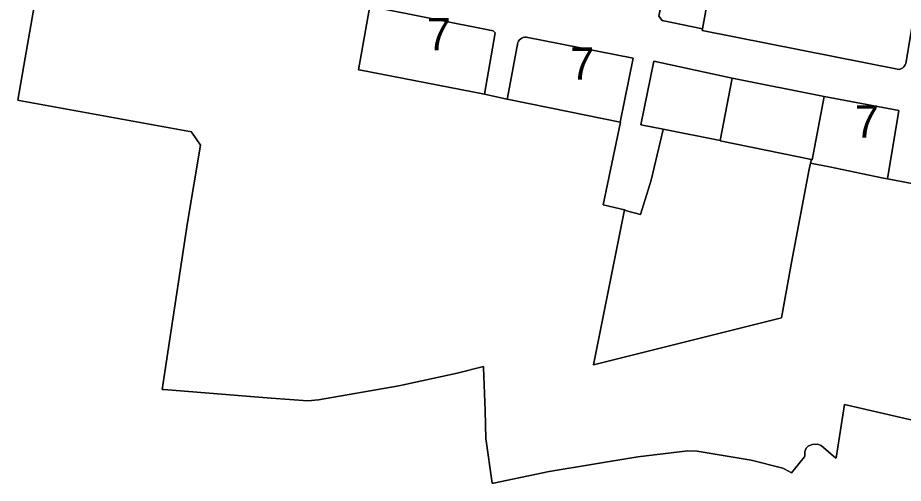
# Model space of a CAD drawing. Extents: x 598968 to 613553, y 4409678 to 4430833.
# Drawn here: x 602980.3 to 603309.2, y 4413969.3 to 4414142.1 of the extents above; entities that cross this region are included whole.
import ezdxf

# ---------------------------------------------------------------- set-up
doc = ezdxf.new("R2010")
doc.units = 0
for name, color, linetype in [('1', 7, 'Continuous'), ('Sòl Rústic Comú', 7, 'Continuous'), ('ZONA 7. CONJUNTS AMB ORDENACIONS ESPECÍFIQUES', 7, 'Continuous')]:
    doc.layers.add(name, color=color, linetype=linetype)

msp = doc.modelspace()

# ---------------------------------------------------------------- linework, layer by layer
at = {"layer": '1'}
for points in [[(603001.3555, 4414231.9552), (602983.0554, 4414127.2462), (602980.3102, 4414111.5388), (602980.8588, 4414111.4381), (603044.7899, 4414099.7029), (603044.9277, 4414099.5046), (603048.1985, 4414094.7989), (603043.3063, 4414066.0493), (603034.0121, 4414004.104), (603034.5665, 4414004.0593), (603074.472, 4414000.8428), (603088.0976, 4413999.8613), (603092.0176, 4414000.2313), (603121.7866, 4414005.4819), (603143.5107, 4414010.1687), (603153.2756, 4414012.6724), (603153.2915, 4414012.2698), (603153.9257, 4413996.196), (603154.1256, 4413985.883), (603156.5673, 4413969.2754), (603157.0371, 4413969.3739), (603177.645, 4413973.6936), (603210.6332, 4413979.0852), (603229.1233, 4413981.3046), (603232.6033, 4413981.1646), (603252.6527, 4413977.8752), (603264.4825, 4413974.9356), (603264.9489, 4413974.6754), (603267.6725, 4413973.1558), (603267.683, 4413973.1687), (603272.4823, 4413979.0458), (603272.5823, 4413979.3158), (603272.6067, 4413981.1244), (603273.058, 4413982.2676), (603273.8408, 4413983.0292), (603275.3116, 4413983.6175), (603277.4779, 4413983.8214), (603278.5922, 4413983.346), (603278.7136, 4413983.2436), (603284.1921, 4413978.6262), (603284.2158, 4413978.7752), (603287.3637, 4413998.5624), (603348.986, 4413984.2884)], [(603312.3244, 4414080.5991), (603303.2677, 4414082.3184), (603301.864, 4414082.5849), (603293.4991, 4414084.3223), (603281.7252, 4414086.7677), (603276.6332, 4414087.7538), (603274.7361, 4414088.1212), (603274.1921, 4414085.9041), (603267.6364, 4414051.2539), (603267.6356, 4414051.2495), (603263.9373, 4414030.7161), (603194.1441, 4414013.2999), (603205.7011, 4414070.8369), (603197.7705, 4414072.7021), (603204.1269, 4414103.2926), (603204.0806, 4414103.3021), (603177.9212, 4414108.6653), (603162.105, 4414111.9079), (603161.8946, 4414111.951), (603153.6604, 4414113.6949), (603153.0486, 4414113.8244), (603107.1357, 4414122.7347), (603106.8792, 4414122.7845), (603111.0376, 4414146.3708)], [(603111.458, 4414146.3147), (603156.871, 4414137.2916), (603157.6073, 4414136.5453), (603153.6604, 4414113.6949), (603161.8946, 4414111.951), (603162.105, 4414111.9079), (603162.2559, 4414112.3704), (603166.0872, 4414132.9854), (603166.3476, 4414133.4655), (603166.6869, 4414133.8934), (603167.0949, 4414134.2562), (603167.5595, 4414134.5432), (603168.0667, 4414134.7457), (603168.6013, 4414134.8575), (603169.1471, 4414134.8754), (603208.8966, 4414127.0859), (603204.0806, 4414103.3021), (603204.1269, 4414103.2926), (603197.7705, 4414072.7021), (603205.7011, 4414070.8369), (603206.3553, 4414070.3923), (603211.5667, 4414069.0964), (603215.5366, 4414081.7763), (603219.9752, 4414100.5883), (603220.0101, 4414100.728), (603211.744, 4414102.3682), (603216.4894, 4414126.0437), (603245.6556, 4414119.7427), (603279.8385, 4414112.9327), (603279.8368, 4414112.9268), (603307.5555, 4414107.6375), (603303.2677, 4414082.3184), (603312.3244, 4414080.5991)]]:
    msp.add_lwpolyline(points, dxfattribs=at)
for points in [[(603310.1154, 4414125.1474), (603309.9234, 4414124.6845), (603309.663, 4414124.2564), (603309.3402, 4414123.8731), (603308.9627, 4414123.5435), (603308.5393, 4414123.2754), (603308.08, 4414123.0752), (603307.5954, 4414122.9474), (603234.4561, 4414137.3361), (603234.5754, 4414137.9637), (603219.612, 4414141.0883), (603218.3425, 4414142.7448), (603220.9165, 4414155.3969), (603220.9193, 4414155.4116), (603220.8963, 4414155.4158), (603226.4961, 4414185.4556), (603317.2152, 4414167.5072)], [(603234.5754, 4414137.9637), (603236.4022, 4414147.5748), (603237.3031, 4414152.4401), (603220.9193, 4414155.4116), (603220.9165, 4414155.3969), (603218.3425, 4414142.7448), (603219.612, 4414141.0883)], [(603245.6556, 4414119.7427), (603216.4894, 4414126.0437), (603211.744, 4414102.3682), (603220.0101, 4414100.728), (603241.1603, 4414096.5311)], [(603275.0694, 4414089.4798), (603241.1603, 4414096.4771), (603241.168, 4414096.5172), (603245.6556, 4414119.7427), (603241.1603, 4414096.5311), (603220.0101, 4414100.728), (603219.9752, 4414100.5883), (603215.5366, 4414081.7763), (603211.5667, 4414069.0964), (603206.3553, 4414070.3923), (603205.7011, 4414070.8369), (603194.1441, 4414013.2999), (603263.9373, 4414030.7161), (603267.6356, 4414051.2495), (603267.6364, 4414051.2539), (603274.1921, 4414085.9041), (603274.7361, 4414088.1212)], [(603279.8368, 4414112.9268), (603279.8385, 4414112.9327), (603245.6556, 4414119.7427), (603241.168, 4414096.5172), (603241.1603, 4414096.4771), (603275.0694, 4414089.4798), (603275.3436, 4414089.4232), (603279.4389, 4414110.8429)]]:
    msp.add_lwpolyline(points, close=True, dxfattribs=at)
at = {"layer": 'Sòl Rústic Comú'}
msp.add_lwpolyline([(603348.986, 4413984.2884), (603287.3637, 4413998.5624), (603284.2158, 4413978.7752), (603284.1921, 4413978.6262), (603278.7136, 4413983.2436), (603278.5922, 4413983.346), (603277.4779, 4413983.8214), (603275.3116, 4413983.6175), (603273.8408, 4413983.0292), (603273.058, 4413982.2676), (603272.6067, 4413981.1244), (603272.5823, 4413979.3158), (603272.4823, 4413979.0458), (603267.683, 4413973.1687), (603267.6725, 4413973.1558), (603264.9489, 4413974.6754), (603264.4825, 4413974.9356), (603252.6527, 4413977.8752), (603232.6033, 4413981.1646), (603229.1233, 4413981.3046), (603210.6332, 4413979.0852), (603177.645, 4413973.6936), (603157.0371, 4413969.3739), (603156.5673, 4413969.2754), (603154.1256, 4413985.883), (603153.9257, 4413996.196), (603153.2915, 4414012.2698), (603153.2756, 4414012.6724), (603143.5107, 4414010.1687), (603121.7866, 4414005.4819), (603092.0176, 4414000.2313), (603088.0976, 4413999.8613), (603074.472, 4414000.8428), (603034.5665, 4414004.0593), (603034.0121, 4414004.104), (603043.3063, 4414066.0493), (603048.1985, 4414094.7989), (603044.9277, 4414099.5046), (603044.7899, 4414099.7029), (602980.8588, 4414111.4381), (602980.3102, 4414111.5388), (602983.0554, 4414127.2462), (603001.3555, 4414231.9552)], dxfattribs=at)
at = {"layer": 'ZONA 7. CONJUNTS AMB ORDENACIONS ESPECÍFIQUES'}
for points in [[(603234.5754, 4414137.9637), (603234.4561, 4414137.3361), (603307.5954, 4414122.9474), (603308.08, 4414123.0752), (603308.5393, 4414123.2754), (603308.9627, 4414123.5435), (603309.3402, 4414123.8731), (603309.663, 4414124.2564), (603309.9234, 4414124.6845), (603310.1154, 4414125.1474), (603317.2152, 4414167.5072), (603226.4961, 4414185.4556), (603220.8963, 4414155.4158), (603220.9193, 4414155.4116), (603237.3031, 4414152.4401), (603236.4022, 4414147.5748)], [(603153.6604, 4414113.6949), (603157.6073, 4414136.5453), (603156.871, 4414137.2916), (603111.458, 4414146.3147), (603111.0376, 4414146.3708), (603106.8792, 4414122.7845), (603107.1357, 4414122.7347), (603153.0486, 4414113.8244)], [(603204.0806, 4414103.3021), (603208.8966, 4414127.0859), (603169.1471, 4414134.8754), (603168.6013, 4414134.8575), (603168.0667, 4414134.7457), (603167.5595, 4414134.5432), (603167.0949, 4414134.2562), (603166.6869, 4414133.8934), (603166.3476, 4414133.4655), (603166.0872, 4414132.9854), (603162.2559, 4414112.3704), (603162.105, 4414111.9079), (603177.9212, 4414108.6653)], [(603303.2677, 4414082.3184), (603307.5555, 4414107.6375), (603279.8368, 4414112.9268), (603279.4389, 4414110.8429), (603275.3436, 4414089.4232), (603275.0694, 4414089.4798), (603274.7361, 4414088.1212), (603276.6332, 4414087.7538), (603281.7252, 4414086.7677), (603293.4991, 4414084.3223), (603301.864, 4414082.5849)]]:
    msp.add_lwpolyline(points, close=True, dxfattribs=at)

# ---------------------------------------------------------------- texts
for p in [(603132.2433, 4414130.0329), (603185.5008, 4414119.0888), (603291.1458, 4414097.6226)]:
    msp.add_text('7', height=12, dxfattribs=at).set_placement(p)

doc.saveas('drawing.dxf')
